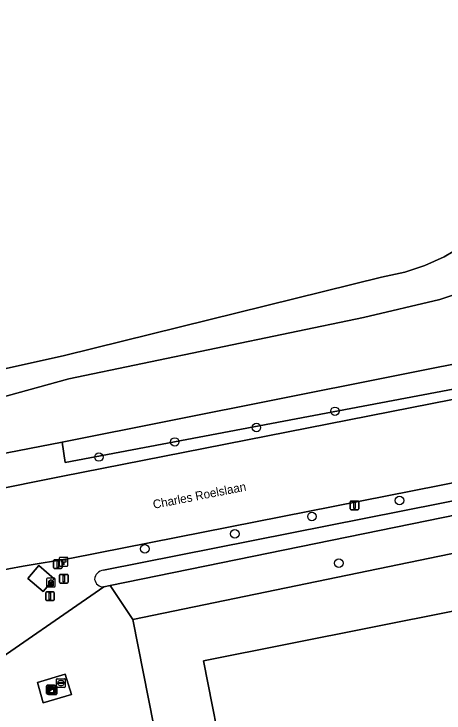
# Model space of a CAD drawing. Extents: x 160203 to 161530, y 379528 to 381797.
# Drawn here: x 160929.7 to 160979.3, y 379917 to 379997.6 of the extents above; entities that cross this region are included whole.
import ezdxf

# ---------------------------------------------------------------- set-up
doc = ezdxf.new("R2010")
doc.units = 0
for name, color, linetype in [('IMGEO_Boom', 7, 'Continuous'), ('IMGEO_Grasland_overig', 7, 'Continuous'), ('IMGEO_Groenvoorziening', 7, 'Continuous'), ('IMGEO_Hectometerpaal', 7, 'Continuous'), ('IMGEO_Hek', 7, 'Continuous'), ('IMGEO_Kast', 7, 'Continuous'), ('IMGEO_Lichtmast', 7, 'Continuous'), ('IMGEO_Loofbos', 7, 'Continuous'), ('IMGEO_Openbare_ruimte_label', 7, 'Continuous'), ('IMGEO_Reclamezuil', 7, 'Continuous'), ('IMGEO_Rijbaan_lokaal_open', 7, 'Continuous'), ('IMGEO_Rioolput', 7, 'Continuous'), ('IMGEO_Terreindeel_open', 7, 'Continuous'), ('IMGEO_Vlaggenmast', 7, 'Continuous'), ('IMGEO_Voetpad_onverhard', 7, 'Continuous'), ('IMGEO_Waterloop', 7, 'Continuous')]:
    doc.layers.add(name, color=color, linetype=linetype)

msp = doc.modelspace()

# ---------------------------------------------------------------- linework, layer by layer
at = {"layer": 'IMGEO_Boom'}
for centre in [(160966.71, 379951.778), (160957.643, 379949.911), (160948.217, 379948.242), (160939.479, 379946.506), (160974.159, 379941.498), (160964.05, 379939.64), (160955.163, 379937.648), (160944.773, 379935.913), (160967.156, 379934.274)]:
    msp.add_circle(centre, 0.489, dxfattribs=at)
at = {"layer": 'IMGEO_Grasland_overig'}
msp.add_lwpolyline([(161008.006, 379908.641), (161006.059, 379919.315), (161005.317, 379923.52), (161015.307, 379925.53), (161014.737, 379928.361), (161022.338, 379929.878), (161022.088, 379931.253), (161025.189, 379933.097), (161027.702, 379935.192), (161029.839, 379937.308), (161030.74, 379938.502), (161032.921, 379938.901), (161031.58, 379945.502), (161031.511, 379945.843), (161030.126, 379945.579), (161024.194, 379944.451), (161025.245, 379937.898), (161013.069, 379935.373), (161000, 379932.662), (160951.544, 379923.025), (160959.272, 379883.804)], dxfattribs=at)
at = {"layer": 'IMGEO_Groenvoorziening'}
for points in [[(161029.658, 379947.483), (161030.126, 379945.579), (161031.511, 379945.843), (161030.736, 379949.662), (161026.674, 379952.839), (161013.911, 379950.345), (161000, 379947.411), (160936.325, 379934.86), (160930.729, 379933.941), (160927.405, 379933.308)], [(160939.993, 379933.455), (160991.806, 379943.722), (161000, 379945.518)], [(160995.56, 379942.876), (160940.767, 379931.705), (160943.379, 379927.759), (161000, 379939.454)], [(160923.141, 379926.741), (160923.562, 379926.803), (160924.695, 379921.196), (160924.737, 379920.983), (160932.53, 379881.598), (160932.652, 379880.978), (160933.604, 379881.066), (160925.646, 379921.61), (160940.056, 379931.56)]]:
    msp.add_lwpolyline(points, dxfattribs=at)
msp.add_lwpolyline([(160931.262, 379932.519), (160932.525, 379933.982), (160934.297, 379932.453), (160933.929, 379932.027), (160933.033, 379930.989)], close=True, dxfattribs=at)
for centre, radius, start, end in [((160940.109, 379932.328), 1.132, 95.86901, 176.07492), ((160939.955, 379932.54), 0.986, 187.83676, 275.86288)]:
    msp.add_arc(centre, radius, start, end, dxfattribs=at)
at = {"layer": 'IMGEO_Hectometerpaal'}
for p, q in [((160934.905, 379934.854), (160934.905, 379934.013)), ((160934.905, 379934.854), (160934.905, 379934.013)), ((160935.821, 379934.938), (160934.98, 379934.938)), ((160935.821, 379934.938), (160934.98, 379934.938)), ((160935.905, 379934.022), (160935.905, 379934.863)), ((160935.905, 379934.022), (160935.905, 379934.863)), ((160934.989, 379933.938), (160935.83, 379933.938)), ((160934.989, 379933.938), (160935.83, 379933.938))]:
    msp.add_line(p, q, dxfattribs=at)
msp.add_lwpolyline([(160935.43, 379934.082), (160935.37, 379934.082), (160935.37, 379934.387), (160935.15, 379934.387), (160935.15, 379934.656), (160935.65, 379934.656), (160935.65, 379934.387), (160935.43, 379934.387), (160935.43, 379934.082)], dxfattribs=at)
for centre, start, end in [((160934.983, 379934.86), 92.4484, 184.28452), ((160934.983, 379934.86), 92.4484, 184.28452), ((160935.827, 379934.86), 2.4484, 94.28452), ((160935.827, 379934.86), 2.4484, 94.28452), ((160934.983, 379934.016), 182.4484, 274.28452), ((160934.983, 379934.016), 182.4484, 274.28452), ((160935.827, 379934.016), 272.4484, 4.28452), ((160935.827, 379934.016), 272.4484, 4.28452)]:
    msp.add_arc(centre, 0.0779, start, end, dxfattribs=at)
at = {"layer": 'IMGEO_Hek'}
msp.add_lwpolyline([(161000, 379932.662), (160951.544, 379923.025), (160959.272, 379883.804)], dxfattribs=at)
at = {"layer": 'IMGEO_Kast'}
for p, q in [((160933.442, 379919.263), (160933.442, 379920.104)), ((160933.442, 379920.104), (160933.442, 379919.263)), ((160933.517, 379920.188), (160934.358, 379920.188)), ((160934.358, 379920.188), (160933.517, 379920.188)), ((160933.611, 379919.213), (160933.611, 379920.054)), ((160933.611, 379920.054), (160933.611, 379919.213)), ((160933.686, 379920.138), (160934.527, 379920.138)), ((160934.527, 379920.138), (160933.686, 379920.138)), ((160934.442, 379920.113), (160934.442, 379919.272)), ((160934.442, 379919.272), (160934.442, 379920.113)), ((160934.611, 379920.063), (160934.611, 379919.222)), ((160934.611, 379919.222), (160934.611, 379920.063)), ((160934.367, 379919.188), (160933.526, 379919.188)), ((160933.526, 379919.188), (160934.367, 379919.188)), ((160934.536, 379919.138), (160933.695, 379919.138)), ((160933.695, 379919.138), (160934.536, 379919.138))]:
    msp.add_line(p, q, dxfattribs=at)
for points in [[(160933.637, 379919.978), (160934.237, 379919.978), (160934.237, 379919.893), (160933.637, 379919.893), (160933.637, 379919.978)], [(160933.637, 379919.803), (160934.237, 379919.803), (160934.237, 379919.314), (160933.637, 379919.314), (160933.637, 379919.803)], [(160933.806, 379919.928), (160934.406, 379919.928), (160934.406, 379919.843), (160933.806, 379919.843), (160933.806, 379919.928)], [(160933.806, 379919.753), (160934.406, 379919.753), (160934.406, 379919.264), (160933.806, 379919.264), (160933.806, 379919.753)]]:
    msp.add_lwpolyline(points, dxfattribs=at)
for centre in [(160933.721, 379919.652), (160933.89, 379919.602)]:
    msp.add_circle(centre, 0.0377, dxfattribs=at)
for centre, start, end in [((160933.52, 379920.11), 92.4484, 184.28452), ((160933.52, 379920.11), 92.4484, 184.28452), ((160933.689, 379920.06), 92.4484, 184.28452), ((160933.689, 379920.06), 92.4484, 184.28452), ((160934.364, 379920.11), 2.4484, 94.28452), ((160934.364, 379920.11), 2.4484, 94.28452), ((160934.533, 379920.06), 2.4484, 94.28452), ((160934.533, 379920.06), 2.4484, 94.28452), ((160933.52, 379919.266), 182.4484, 274.28452), ((160933.52, 379919.266), 182.4484, 274.28452), ((160933.689, 379919.216), 182.4484, 274.28452), ((160933.689, 379919.216), 182.4484, 274.28452), ((160934.364, 379919.266), 272.4484, 4.28452), ((160934.364, 379919.266), 272.4484, 4.28452), ((160934.533, 379919.216), 272.4484, 4.28452), ((160934.533, 379919.216), 272.4484, 4.28452)]:
    msp.add_arc(centre, 0.0779, start, end, dxfattribs=at)
at = {"layer": 'IMGEO_Lichtmast'}
for p, q in [((160968.472, 379940.528), (160968.472, 379941.328)), ((160968.472, 379941.328), (160968.472, 379940.528)), ((160968.572, 379941.428), (160969.362, 379941.428)), ((160969.362, 379941.428), (160968.572, 379941.428)), ((160969.462, 379941.328), (160969.462, 379940.528)), ((160969.462, 379940.528), (160969.462, 379941.328)), ((160969.362, 379940.428), (160968.572, 379940.428)), ((160968.572, 379940.428), (160969.362, 379940.428)), ((160934.229, 379933.758), (160934.229, 379934.558)), ((160934.229, 379934.558), (160934.229, 379933.758)), ((160934.329, 379934.658), (160935.119, 379934.658)), ((160935.119, 379934.658), (160934.329, 379934.658)), ((160935.219, 379934.558), (160935.219, 379933.758)), ((160935.219, 379933.758), (160935.219, 379934.558)), ((160935.119, 379933.658), (160934.329, 379933.658)), ((160934.329, 379933.658), (160935.119, 379933.658))]:
    msp.add_line(p, q, dxfattribs=at)
for points in [[(160968.892, 379941.303), (160969.042, 379941.303), (160969.042, 379940.553), (160968.892, 379940.553), (160968.892, 379941.303)], [(160934.649, 379934.533), (160934.799, 379934.533), (160934.799, 379933.783), (160934.649, 379933.783), (160934.649, 379934.533)]]:
    msp.add_lwpolyline(points, dxfattribs=at)
for centre, start, end in [((160968.572, 379941.328), 90, 180), ((160968.572, 379941.328), 90, 180), ((160969.362, 379941.328), 0, 90), ((160969.362, 379941.328), 360, 90), ((160968.572, 379940.528), 180, 270), ((160968.572, 379940.528), 180, 270), ((160969.362, 379940.528), 270, 0), ((160969.362, 379940.528), 270, 0), ((160934.329, 379934.558), 90, 180), ((160934.329, 379934.558), 90, 180), ((160935.119, 379934.558), 0, 90), ((160935.119, 379934.558), 360, 90), ((160934.329, 379933.758), 180, 270), ((160934.329, 379933.758), 180, 270), ((160935.119, 379933.758), 270, 0), ((160935.119, 379933.758), 270, 0)]:
    msp.add_arc(centre, 0.1, start, end, dxfattribs=at)
at = {"layer": 'IMGEO_Loofbos'}
for points in [[(160910.327, 380007.409), (160920.602, 379955.987), (160921, 379955.813), (160922.449, 379955.516), (160923.188, 379955.482), (160935.494, 379958.213), (160972.092, 379967.237), (160974.767, 379967.81), (160977.079, 379968.582), (160979.298, 379969.591), (160980.332, 379970.199), (160981.399, 379970.826), (160983.359, 379972.274), (160984.32, 379973.153), (160985.158, 379973.92), (160986.774, 379975.744), (160988.191, 379977.727), (160992.684, 379987.962), (160993.627, 379989.939), (160997.664, 379999.984)], [(161093.454, 379977.21), (161081.741, 379975.129), (161026.757, 379964.623), (161005.514, 379960.734), (161000, 379958.372), (160998.654, 379957.795), (160935.592, 379945.881), (160935.239, 379948.227), (160922.706, 379945.785), (160921.668, 379948.198), (160919.01, 379947.114), (160919.54, 379945.851)], [(160926.483, 379942.53), (160935.112, 379944.265), (160989.654, 379954.98), (160999.998, 379956.482), (161003.088, 379956.98), (161017.577, 379958.366)]]:
    msp.add_lwpolyline(points, dxfattribs=at)
for points in [[(160997.906, 379960.687), (161000, 379962.09), (161004.745, 379965.268), (161019.862, 379967.505), (160990.026, 379967.436), (160987.186, 379967.088), (160983.541, 379966.218), (160978.788, 379964.646), (160970.004, 379962.58), (160935.992, 379955.526), (160925.518, 379952.646), (160924.211, 379951.846), (160923.099, 379950.792), (160922.23, 379949.53), (160921.668, 379948.198), (160922.706, 379945.785), (160935.239, 379948.227)], [(160952.452, 379881.869), (160959.428, 379883.014), (160959.272, 379883.804), (160951.544, 379923.025), (161000, 379932.662), (161013.069, 379935.373), (161025.245, 379937.898), (161024.194, 379944.451), (161011.409, 379941.81), (161000, 379939.454), (160943.379, 379927.759)], [(160943.379, 379927.759), (160940.767, 379931.705), (160940.056, 379931.56), (160925.646, 379921.61), (160933.604, 379881.066), (160938.808, 379881.547), (160947.921, 379881.474), (160949.601, 379881.544), (160952.452, 379881.869)], [(160933.058, 379918.173), (160932.406, 379920.516), (160935.579, 379921.458), (160936.315, 379919.133)]]:
    msp.add_lwpolyline(points, close=True, dxfattribs=at)
at = {"layer": 'IMGEO_Reclamezuil'}
for p, q in [((160933.431, 379932.431), (160933.431, 379931.623)), ((160933.431, 379932.431), (160933.431, 379931.623)), ((160934.333, 379932.525), (160933.525, 379932.525)), ((160934.333, 379932.525), (160933.525, 379932.525)), ((160934.06, 379932.067), (160933.798, 379932.067)), ((160934.427, 379931.623), (160934.427, 379932.431)), ((160934.427, 379931.623), (160934.427, 379932.431)), ((160933.525, 379931.529), (160934.333, 379931.529)), ((160933.525, 379931.529), (160934.333, 379931.529)), ((160933.798, 379931.98), (160934.06, 379931.98)), ((160934.06, 379931.865), (160933.798, 379931.865)), ((160933.798, 379931.778), (160934.06, 379931.778))]:
    msp.add_line(p, q, dxfattribs=at)
msp.add_lwpolyline([(160933.679, 379932.198), (160933.929, 379932.368), (160934.179, 379932.198), (160934.179, 379931.675), (160933.679, 379931.675), (160933.679, 379932.198)], dxfattribs=at)
for centre, radius, start, end in [((160933.525, 379932.431), 0.0946, 90, 180), ((160933.525, 379932.431), 0.0946, 90, 180), ((160933.798, 379932.024), 0.0436, 89.97397, 270.02603), ((160934.06, 379932.024), 0.0436, 269.97397, 90.02603), ((160934.333, 379932.431), 0.0946, 0, 90), ((160934.333, 379932.431), 0.0946, 0, 90), ((160933.525, 379931.623), 0.0946, 180, 270), ((160933.525, 379931.623), 0.0946, 180, 270), ((160933.798, 379931.821), 0.0436, 89.97397, 270.02603), ((160934.06, 379931.821), 0.0436, 269.97397, 90.02603), ((160934.333, 379931.623), 0.0946, 270, 0), ((160934.333, 379931.623), 0.0946, 270, 0)]:
    msp.add_arc(centre, radius, start, end, dxfattribs=at)
at = {"layer": 'IMGEO_Rijbaan_lokaal_open'}
for points in [[(161017.577, 379958.366), (161003.088, 379956.98), (160999.998, 379956.482), (160989.654, 379954.98), (160935.112, 379944.265), (160926.483, 379942.53)], [(160927.405, 379933.308), (160930.729, 379933.941), (160936.325, 379934.86), (161000, 379947.411), (161013.911, 379950.345), (161026.674, 379952.839), (161034.962, 379954.474), (161044.221, 379956.334)]]:
    msp.add_lwpolyline(points, dxfattribs=at)
at = {"layer": 'IMGEO_Rioolput'}
for p, q in [((160934.591, 379920.028), (160934.591, 379920.88)), ((160934.666, 379920.954), (160935.518, 379920.954)), ((160935.592, 379920.88), (160935.592, 379920.028)), ((160935.518, 379919.954), (160934.666, 379919.954)), ((160934.85, 379920.448), (160934.85, 379920.46)), ((160935.288, 379920.411), (160934.89, 379920.411)), ((160934.893, 379920.497), (160935.291, 379920.497)), ((160935.102, 379920.174), (160935.077, 379920.174)), ((160935.079, 379920.734), (160935.104, 379920.734)), ((160935.334, 379920.46), (160935.334, 379920.448))]:
    msp.add_line(p, q, dxfattribs=at)
for points in [[(160934.591, 379920.028), (160934.591, 379920.88)], [(160934.666, 379920.954), (160935.518, 379920.954)], [(160935.592, 379920.88), (160935.592, 379920.028)], [(160935.518, 379919.954), (160934.666, 379919.954)]]:
    msp.add_lwpolyline(points, dxfattribs=at)
for centre, radius, start, end in [((160934.668, 379920.878), 0.0765, 91.55205, 178.44795), ((160934.668, 379920.878), 0.0765, 91.55205, 178.44795), ((160935.516, 379920.878), 0.0765, 1.55205, 88.44795), ((160935.516, 379920.878), 0.0765, 1.55205, 88.44795), ((160934.668, 379920.03), 0.0765, 181.55205, 268.44795), ((160934.668, 379920.03), 0.0765, 181.55205, 268.44795), ((160934.89, 379920.457), 0.0403, 85.87752, 175.75265), ((160934.887, 379920.447), 0.0366, 178.93798, 274.71019), ((160935.291, 379920.454), 0.043, 264.86636, 352.45326), ((160935.295, 379920.459), 0.0386, 1.73085, 96.63898), ((160935.516, 379920.03), 0.0765, 271.55205, 358.44795), ((160935.516, 379920.03), 0.0765, 271.55205, 358.44795)]:
    msp.add_arc(centre, radius, start, end, dxfattribs=at)
for centre, major_axis, ratio, start_param, end_param in [((160935.078, 379920.454), (-0.387, 0.002), 0.722429, 4.712389, 7.853982), ((160935.103, 379920.454), (-0.39, 0.002), 0.717154, 1.570796, 4.712389)]:
    msp.add_ellipse(centre, major_axis=major_axis, ratio=ratio, start_param=start_param, end_param=end_param, dxfattribs=at)
at = {"layer": 'IMGEO_Terreindeel_open'}
for points in [[(160932.525, 379933.982), (160931.262, 379932.519), (160933.033, 379930.989), (160933.929, 379932.027), (160934.297, 379932.453)], [(160933.058, 379918.173), (160936.315, 379919.133), (160935.579, 379921.458), (160932.406, 379920.516)]]:
    msp.add_lwpolyline(points, close=True, dxfattribs=at)
at = {"layer": 'IMGEO_Vlaggenmast'}
for p, q in [((160934.922, 379932.074), (160934.922, 379932.874)), ((160934.922, 379932.874), (160934.922, 379932.074)), ((160935.022, 379932.974), (160935.812, 379932.974)), ((160935.812, 379932.974), (160935.022, 379932.974)), ((160935.912, 379932.874), (160935.912, 379932.074)), ((160935.912, 379932.074), (160935.912, 379932.874)), ((160935.812, 379931.974), (160935.022, 379931.974)), ((160935.022, 379931.974), (160935.812, 379931.974)), ((160933.332, 379930.058), (160933.332, 379930.858)), ((160933.332, 379930.858), (160933.332, 379930.058)), ((160933.432, 379930.958), (160934.222, 379930.958)), ((160934.222, 379930.958), (160933.432, 379930.958)), ((160934.322, 379930.858), (160934.322, 379930.058)), ((160934.322, 379930.058), (160934.322, 379930.858)), ((160934.222, 379929.958), (160933.432, 379929.958)), ((160933.432, 379929.958), (160934.222, 379929.958))]:
    msp.add_line(p, q, dxfattribs=at)
for points in [[(160935.342, 379932.849), (160935.492, 379932.849), (160935.492, 379932.099), (160935.342, 379932.099), (160935.342, 379932.849)], [(160933.752, 379930.833), (160933.902, 379930.833), (160933.902, 379930.083), (160933.752, 379930.083), (160933.752, 379930.833)]]:
    msp.add_lwpolyline(points, dxfattribs=at)
for centre, start, end in [((160935.022, 379932.874), 90, 180), ((160935.022, 379932.874), 90, 180), ((160935.812, 379932.874), 0, 90), ((160935.812, 379932.874), 360, 90), ((160935.022, 379932.074), 180, 270), ((160935.022, 379932.074), 180, 270), ((160935.812, 379932.074), 270, 0), ((160935.812, 379932.074), 270, 0), ((160933.432, 379930.858), 90, 180), ((160933.432, 379930.858), 90, 180), ((160934.222, 379930.858), 0, 90), ((160934.222, 379930.858), 360, 90), ((160933.432, 379930.058), 180, 270), ((160933.432, 379930.058), 180, 270), ((160934.222, 379930.058), 270, 0), ((160934.222, 379930.058), 270, 0)]:
    msp.add_arc(centre, 0.1, start, end, dxfattribs=at)
at = {"layer": 'IMGEO_Voetpad_onverhard'}
msp.add_lwpolyline([(160925.518, 379952.646), (160935.992, 379955.526), (160970.004, 379962.58), (160978.788, 379964.646), (160983.541, 379966.218), (160987.186, 379967.088), (160990.026, 379967.436), (161019.862, 379967.505), (161029.768, 379968.971), (161043.296, 379971.789), (160995.525, 379971.689), (160990.608, 379972.392), (160980.332, 379970.199), (160979.298, 379969.591), (160977.079, 379968.582), (160974.767, 379967.81), (160972.092, 379967.237), (160935.494, 379958.213), (160923.188, 379955.482)], dxfattribs=at)
at = {"layer": 'IMGEO_Waterloop'}
msp.add_lwpolyline([(160998.654, 379957.795), (161000, 379958.372), (160997.906, 379960.687), (160935.239, 379948.227), (160935.592, 379945.881)], close=True, dxfattribs=at)
for points in [[(161000, 379945.518), (160991.806, 379943.722), (160939.993, 379933.455)], [(160940.056, 379931.56), (160940.767, 379931.705), (160995.56, 379942.876)]]:
    msp.add_lwpolyline(points, dxfattribs=at)
for centre, radius, start, end in [((160940.109, 379932.328), 1.132, 95.86901, 176.07492), ((160939.955, 379932.54), 0.986, 187.83676, 275.86288)]:
    msp.add_arc(centre, radius, start, end, dxfattribs=at)

# ---------------------------------------------------------------- texts
at = {"layer": 'IMGEO_Openbare_ruimte_label'}
msp.add_text('Charles Roelslaan', height=1, rotation=11.13011, dxfattribs=at).set_placement((160945.807, 379940.527))

doc.saveas('drawing.dxf')
